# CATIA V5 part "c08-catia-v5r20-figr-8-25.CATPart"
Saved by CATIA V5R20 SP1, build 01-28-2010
Part number: Part1
Bounding box of the stored display mesh (mm): x -50 to 50, y -62.5 to 62.5, z 0 to 10
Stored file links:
  D:\v5_r20\psrt_files_downloaded\c08-catia-v5r20-prt\c08-catia-v5r20-figr-8-25.CATPart
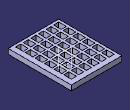
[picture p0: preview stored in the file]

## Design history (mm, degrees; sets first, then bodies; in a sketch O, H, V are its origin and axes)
Body1 (main body)
  Sketch1 on xy-plane, origin (0, 0, 0), H (1, 0, 0), V (0, 1, 0)
    line L1 (-50, 62.5) -> (50, 62.5)
    line L2 (50, 62.5) -> (50, -62.5)
    line L3 (50, -62.5) -> (-50, -62.5)
    line L4 (-50, -62.5) -> (-50, 62.5)
    axis line L5 (50, -62.5) -> (-50, 62.5)
    length L3 = 100
    length L2 = 125
    horizontal: L1 H, L3 H
    vertical: L2 V, L4 V
    midpoint: O L5
  Pad1: profile Sketch1, direction (0, 0, 1), length 10
  Sketch2 on face of Pad1, origin (0, 0, 10), H (1, 0, 0), V (0, 1, 0)
    line L1 (40, -57.5) -> (30, -57.5)
    line L2 (30, -57.5) -> (30, -42.5)
    line L3 (30, -42.5) -> (40, -42.5)
    line L4 (40, -42.5) -> (40, -57.5)
    reference projected line E1 (-50, -62.5) -> (50, -62.5) from edge [face of Pad1 | face of Pad1]
    reference projected line E2 (50, -62.5) -> (50, 62.5) from edge [face of Pad1 | face of Pad1]
    length L1 = 10
    length L4 = 15
    distance L1 E1 = 5
    distance L4 E2 = 10
    horizontal: L1 H, L3 H
    vertical: L2 V, L4 V
  Pocket1: profile Sketch2, direction (0, 0, -1), through (limit type 3)
  RectPattern1: of Pocket1, direction 1 instances 6, spacing 19, along edge [face of Pad1 | face of Pad1], direction 2 instances 6, spacing 15, along edge [face of Pad1 | face of Pad1] reversed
